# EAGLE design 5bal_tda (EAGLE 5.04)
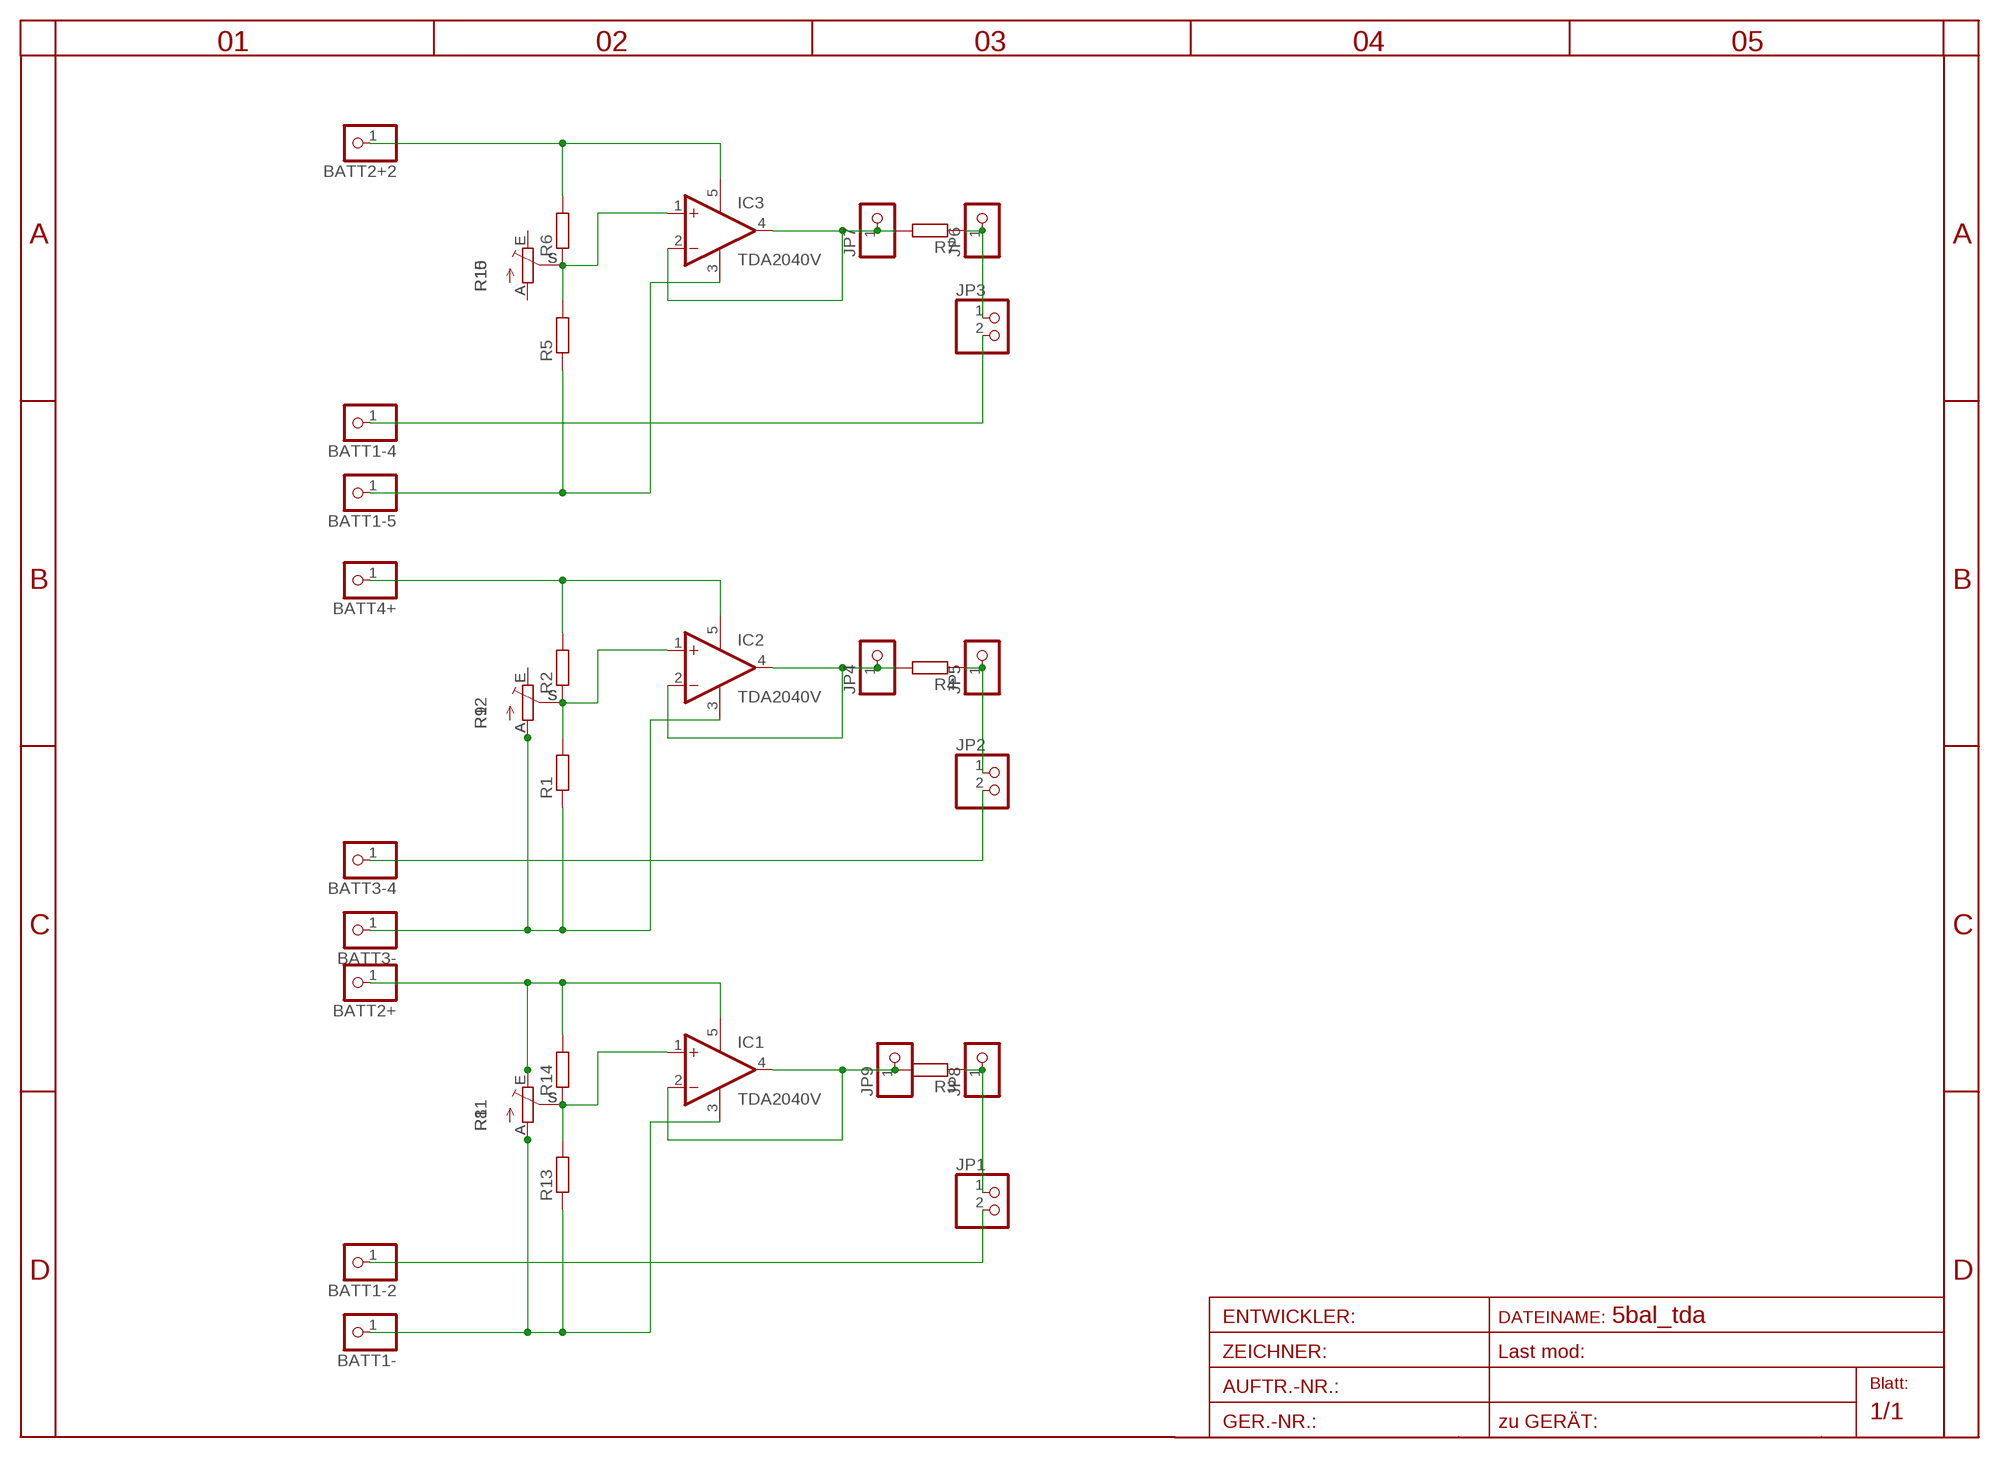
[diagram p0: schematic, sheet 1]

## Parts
BATT1-  PINHD-1X1  [1X01]
BATT1-2  PINHD-1X1  [1X01]
BATT1-4  PINHD-1X1  [1X01]
BATT1-5  PINHD-1X1  [1X01]
BATT2+  PINHD-1X1  [1X01]
BATT2+2  PINHD-1X1  [1X01]
BATT3-  PINHD-1X1  [1X01]
BATT3-4  PINHD-1X1  [1X01]
BATT4+  PINHD-1X1  [1X01]
IC1  TDA2040V  [CB360]
IC2  TDA2040V  [CB360]
IC3  TDA2040V  [CB360]
JP1  PINHD-1X2  [1X02]
JP2  PINHD-1X2  [1X02]
JP3  PINHD-1X2  [1X02]
JP4  PINHD-1X1  [1X01]
JP5  PINHD-1X1  [1X01]
JP6  PINHD-1X1  [1X01]
JP7  PINHD-1X1  [1X01]
JP8  PINHD-1X1  [1X01]
JP9  PINHD-1X1  [1X01]
R1  R-EU_0204/5  [0204/5]
R2  R-EU_0204/7  [0204/7]
R3  R-EU_0411/15  [0411/15]
R4  R-EU_0411/15  [0411/15]
R5  R-EU_0204/5  [0204/5]
R6  R-EU_0204/5  [0204/5]
R7  R-EU_0309/10  [0309/10]
R8  TRIM_EU-LI15  [LI15]
R9  TRIM_EU-LI15  [LI15]
R10  TRIM_EU-LI15  [LI15]
R11  TRIM_EU-CA6V  [CA6V]
R12  TRIM_EU-CA6V  [CA6V]
R13  R-EU_0204/5  [0204/5]
R14  R-EU_0204/7  [0204/7]
R15  TRIM_EU-CA6V  [CA6V]

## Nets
B1+-2: BATT1-2.1 JP1.2
B1-: BATT1-.1 IC1.3(V-) R8.A R11.A R13.1
B2+: BATT2+.1 IC1.5(V+) R8.E R11.E R14.2
B3+-4: BATT3-4.1 JP2.2
B3-: BATT3-.1 IC2.3(V-) R1.1 R9.A R12.A
B4+: BATT4+.1 IC2.5(V+) R2.2
INV1: IC1.2(-IN) IC1.4(OUT) JP9.1 R3.2
MINUS: BATT1-5.1 IC3.3(V-) R5.1
N$1: JP1.1 JP8.1 R3.1
N$3: JP2.1 JP5.1 R4.1
N$4: IC2.1(+IN) R1.2 R2.1 R9.S R12.S
N$5: IC2.2(-IN) IC2.4(OUT) JP4.1 R4.2
N$6: JP3.1 JP6.1 R7.1
N$7: R9.E R12.E
N$8: IC3.1(+IN) R5.2 R6.1 R10.S R15.S
N$9: IC3.2(-IN) IC3.4(OUT) JP7.1 R7.2
N$10: R10.A R15.A
N$11: R10.E R15.E
NINV1: IC1.1(+IN) R8.S R11.S R13.2 R14.1
PLUS: BATT2+2.1 IC3.5(V+) R6.2
PLUSMINUS: BATT1-4.1 JP3.2

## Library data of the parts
BATT1- BATT1-2 BATT1-4 BATT1-5 BATT2+ BATT2+2 BATT3- BATT3-4 BATT4+ JP4-JP9 = pinhead:PINHD-1X1: PIN HEADER
IC1-IC3 = linear:TDA2040: Power OP AMP
JP1-JP3 = pinhead:PINHD-1X2: PIN HEADER
R1-R7 R13 R14 = rcl-2:R-EU_: RESISTOR, European symbol
R8-R12 R15 = pot:TRIM_EU-: POTENTIOMETER

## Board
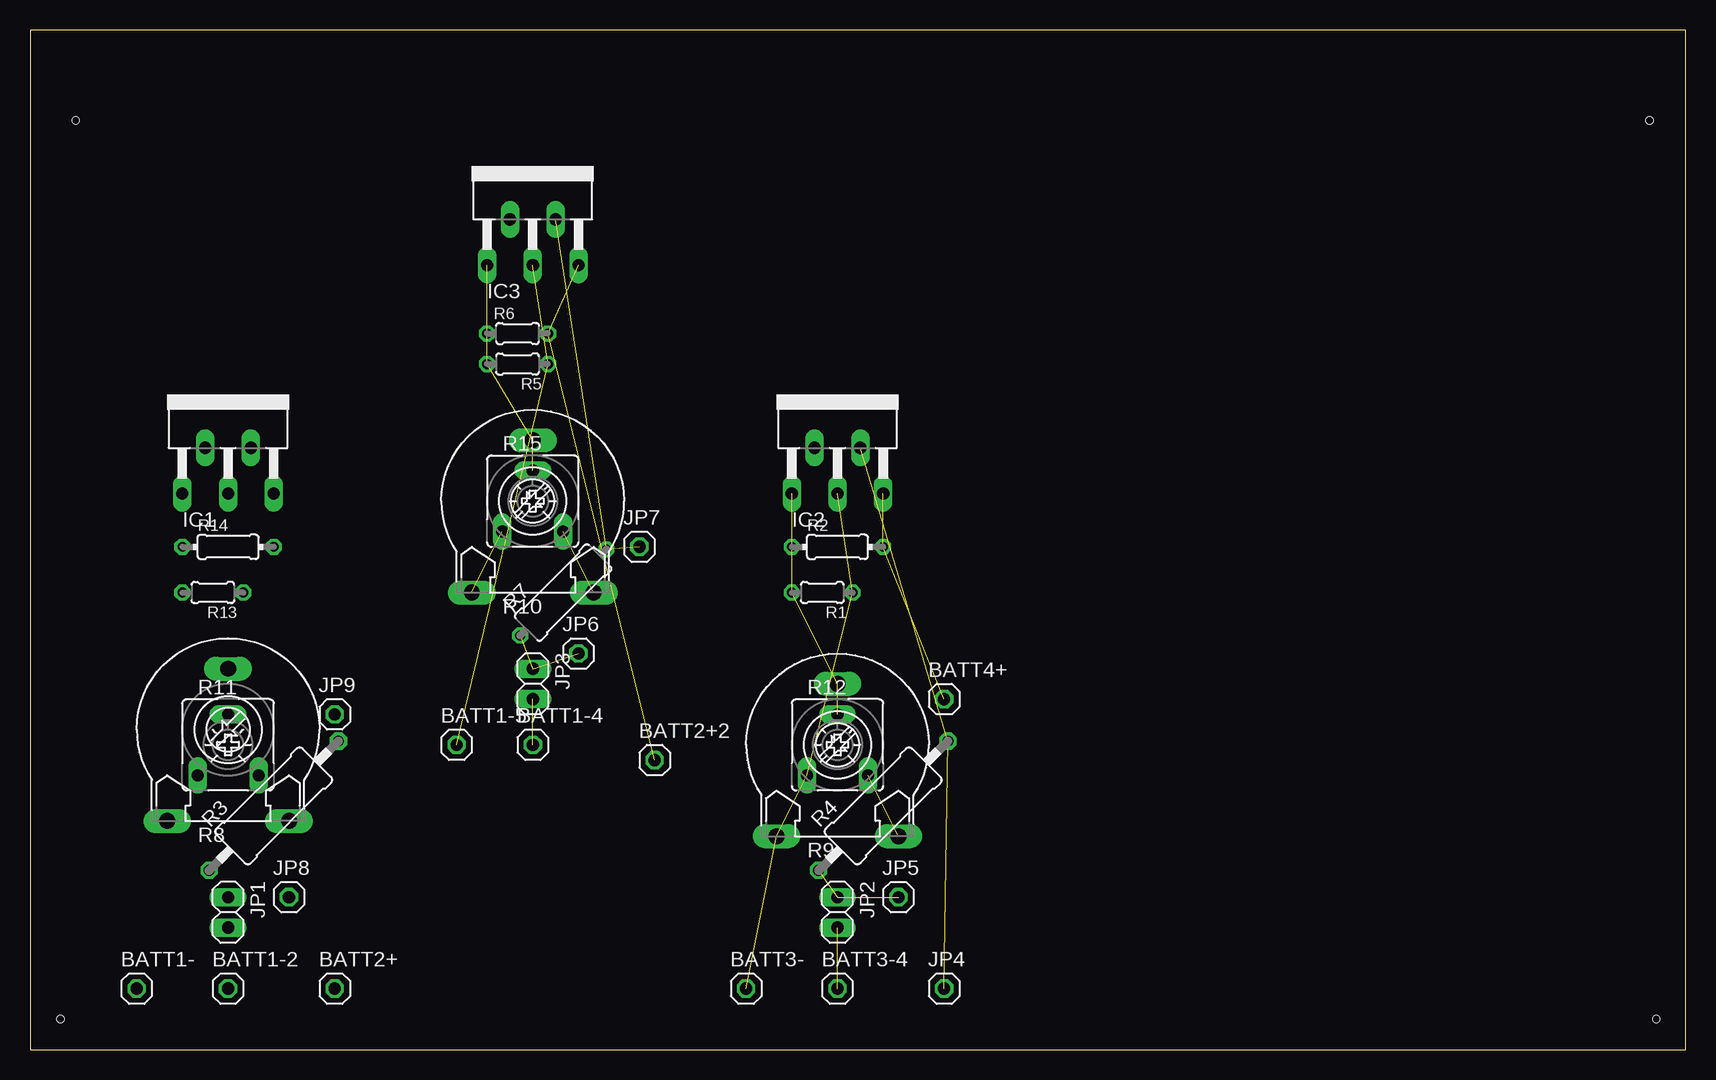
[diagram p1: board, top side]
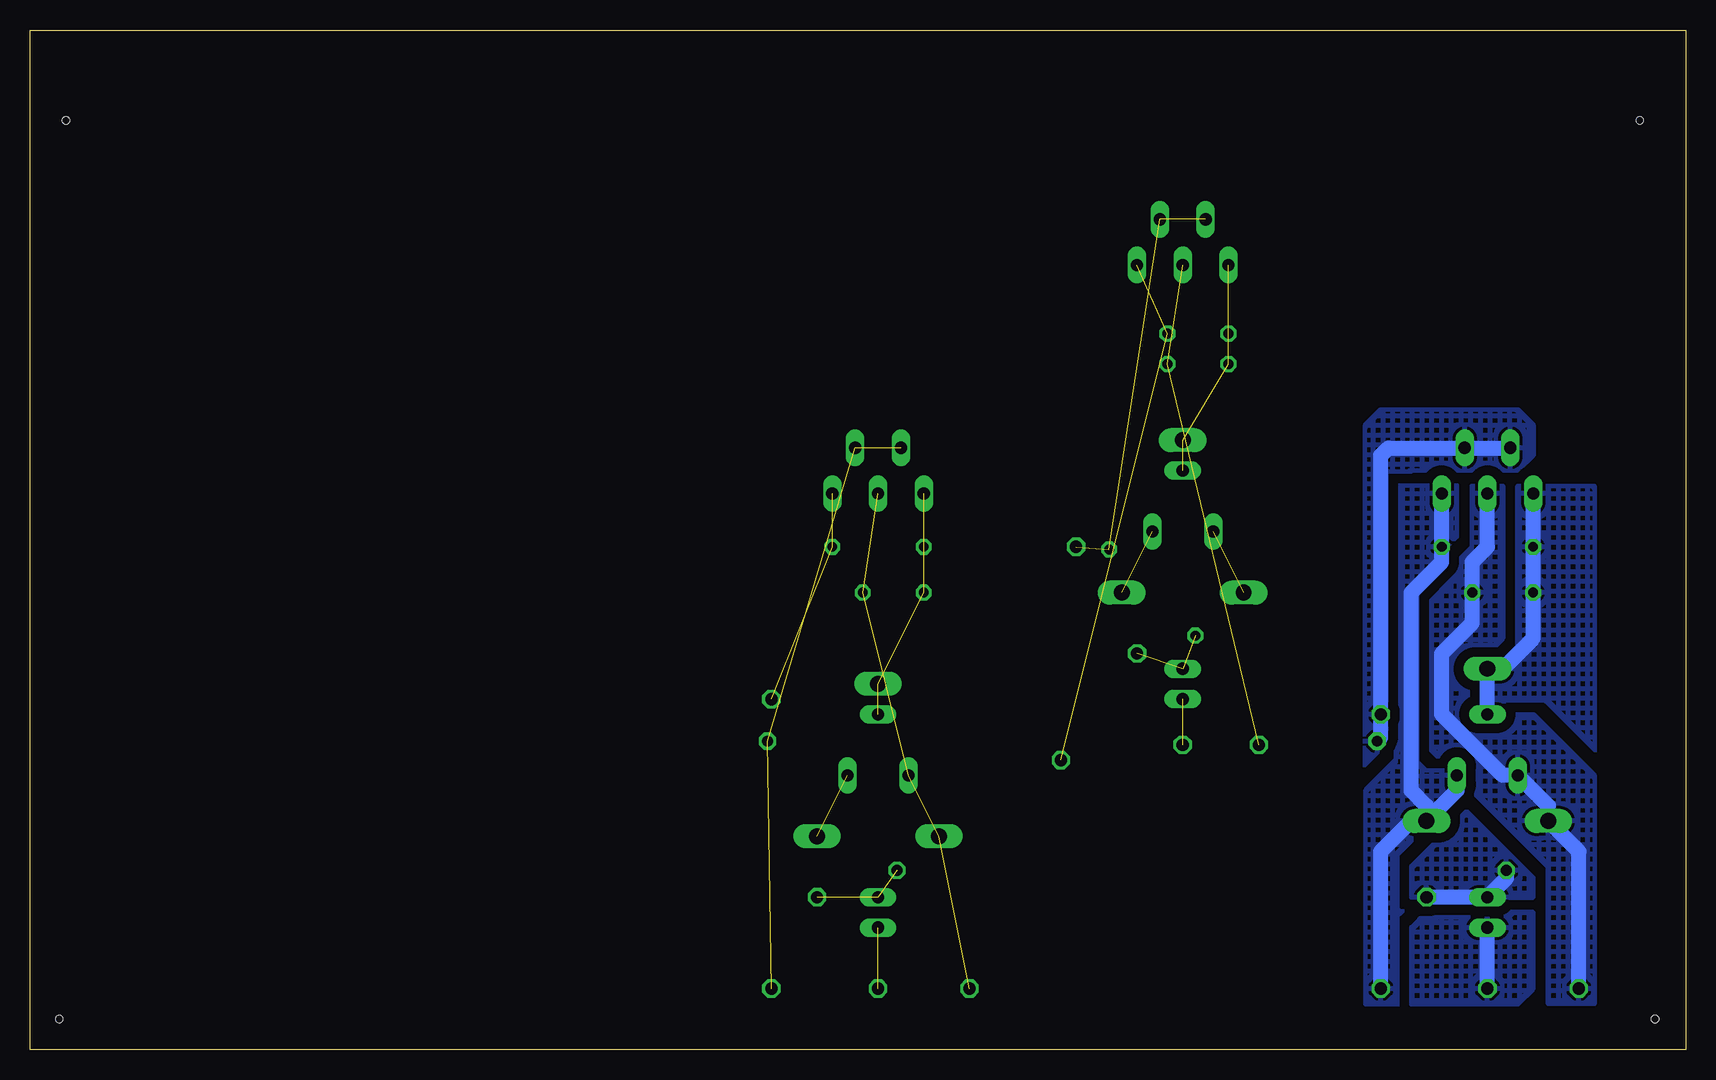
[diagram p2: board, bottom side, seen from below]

Size 138 x 85 mm. Coordinates in mm from the lower left corner, seen from the top.
Outline: 0,0 138,0 138,85 0,85 0,0
Copper layers (1*16): Top 0.035mm / dielectric 1.5mm / Bottom 0.035mm
Design rules "default": minimum track width 10mil, minimum drill 24mil, track to track 8mil, track to pad 8mil, pad to pad 8mil, via to via 8mil, smd to smd 8mil, copper to edge 40mil, drill to drill 8mil, minimum pad ring 10mil, minimum via ring 8mil, stop-mask expansion 4mil, vias tented up to drill 0mil, thermal gap 10mil
Holes 0.6 mm at 2.54,2.54 135.56,2.54 135,77.47 3.81,77.47

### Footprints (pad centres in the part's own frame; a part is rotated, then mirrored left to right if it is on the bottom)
1X01 = drill 1.016 octagon: 1 0,0
CB360 = drill 1.016 long: 1 -3.81,-8.255; 2 -1.905,-4.445; 3 0,-8.255; 4 1.905,-4.445; 5 3.81,-8.255
1X02 = drill 1.016 long: 1 -1.27,0; 2 1.27,0
0204/5 = drill 0.813 octagon: 1 -2.54,0; 2 2.54,0
0204/7 = drill 0.813 octagon: 1 -3.81,0; 2 3.81,0
0411/15 = drill 0.914 octagon: 1 -7.62,0; 2 7.62,0
0309/10 = drill 0.813 octagon: 1 -5.08,0; 2 5.08,0
LI15 = drill 1.321 long: A -5.08,-7.62; E 5.08,-7.62; S 0,5.08
CA6V = drill 1.016 long: A -2.54,-2.54; E 2.54,-2.54; S 0,2.54

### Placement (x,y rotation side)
BATT1-  8.89,5.08 0 top
BATT1-2  16.51,5.08 0 top
BATT1-4  41.91,25.4 0 top
BATT1-5  35.56,25.4 0 top
BATT2+  25.4,5.08 0 top
BATT2+2  52.07,24.13 0 top
BATT3-  59.69,5.08 0 top
BATT3-4  67.31,5.08 0 top
BATT4+  76.2,29.21 0 top
IC1  16.51,54.61 0 top
IC2  67.31,54.61 0 top
IC3  41.91,73.66 0 top
JP1  16.51,11.43 270 top
JP2  67.31,11.43 270 top
JP3  41.91,30.48 270 top
JP4  76.2,5.08 0 top
JP5  72.39,12.7 0 top
JP6  45.72,33.02 0 top
JP7  50.8,41.91 0 top
JP8  21.59,12.7 0 top
JP9  25.4,27.94 0 top
R1  66.04,38.1 180 top
R2  67.31,41.91 0 top
R3  20.32,20.32 45 top
R4  71.12,20.32 45 top
R5  40.64,57.15 180 top
R6  40.64,59.69 0 top
R7  44.45,38.1 45 top
R8  16.51,26.67 0 top
R9  67.31,25.4 0 top
R10  41.91,45.72 0 top
R11  16.51,25.4 0 top
R12  67.31,25.4 0 top
R13  15.24,38.1 180 top
R14  16.51,41.91 0 top
R15  41.91,45.72 0 top

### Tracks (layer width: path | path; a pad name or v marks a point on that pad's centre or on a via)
B1+-2
  Bottom 1.27: BATT1-2.1 JP1.2
  pour Bottom (isolate 0.813, rank 2, hatched): 12.7,11.43 21.59,11.43 22.86,10.16 22.86,3.81 13.97,3.81 12.7,5.08
B1-
  Bottom 1.27: BATT1-.1 8.89,16.51 R8.A 11.43,20.32 R11.A 15.24,22.86 20.32,27.94 20.32,33.02 17.78,35.56 R13.1 17.78,40.64 16.51,41.91 IC1.3
  pour Bottom (isolate 0.813, hatched): 11.43,3.81 11.43,15.24 21.59,25.4 21.59,38.1 17.78,41.91 17.78,46.99 15.24,46.99 15.24,34.29 17.78,31.75 17.78,29.21 16.51,27.94 12.7,27.94 7.62,22.86 7.62,3.81
B2+
  Bottom 1.27: R8.E 22.86,19.05 25.4,16.51 BATT2+.1 | IC1.5 R14.2 20.32,40.64 22.86,38.1 22.86,21.59 21.59,20.32 R8.E | R11.E 19.05,21.59 R8.E
  pour Bottom (isolate 0.813, rank 4, hatched): 19.05,46.99 24.13,46.99 24.13,24.13 26.67,21.59 26.67,3.81 22.86,3.81 22.86,17.78 19.05,21.59
B3+-4  (1 unrouted)
B3-  (4 unrouted)
B4+  (2 unrouted)
INV1
  Bottom 1.27: IC1.2 IC1.4 24.77,50.16 25.4,49.53 JP9.1 25.4,26.02 R3.2
  pour Bottom (isolate 0.813, rank 5, hatched): 26.67,22.86 26.67,52.07 25.4,53.34 13.97,53.34 12.7,52.07 12.7,49.53 13.97,48.26 22.86,48.26 24.13,46.99 24.13,24.13
MINUS  (2 unrouted)
N$1
  Bottom 1.27: JP8.1 JP1.1 14.93,14.28 R3.1
  pour Bottom (isolate 0.813, rank 3, hatched): 17.78,20.32 22.86,15.24 22.86,12.7 12.7,12.7 12.7,15.24
N$3  (2 unrouted)
N$4  (4 unrouted)
N$5  (3 unrouted)
N$6  (2 unrouted)
N$7  (1 unrouted)
N$8  (4 unrouted)
N$9  (3 unrouted)
N$10  (1 unrouted)
N$11  (1 unrouted)
NINV1
  Bottom 1.27: R11.S R8.S 15.24,31.75 12.7,34.29 R13.2 R14.1 IC1.1
  pour Bottom (isolate 0.813, rank 4, hatched): 13.97,46.99 7.62,46.99 7.62,24.13 13.97,24.13 17.78,27.94 17.78,33.02 15.24,35.56
PLUS  (2 unrouted)
PLUSMINUS  (1 unrouted)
